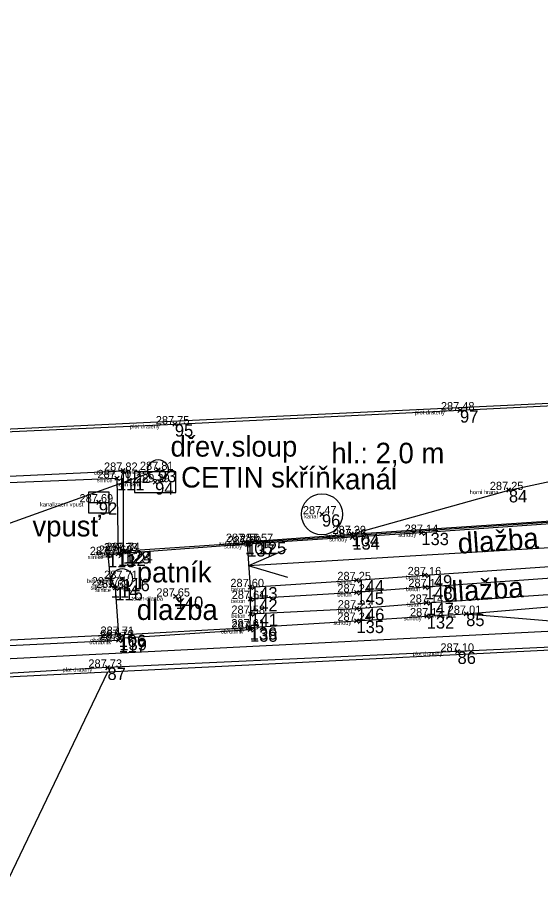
# Model space of a CAD drawing. Extents: x -456675 to -456278, y -1112395 to -1112217.
# Drawn here: x -456350.1 to -456337.38, y -1112310.69 to -1112289.29 of the extents above; entities that cross this region are included whole.
import ezdxf

# ---------------------------------------------------------------- set-up
doc = ezdxf.new("R2010")
doc.units = 0
for name, color, linetype in [('Cislo_bodu', 7, 'Continuous'), ('g_beton', 7, 'Continuous'), ('g_CETIN', 7, 'Continuous'), ('g_chodniky', 7, 'Continuous'), ('g_dalsi_prvky_polohopisu', 7, 'Continuous'), ('g_elektrina', 7, 'Continuous'), ('g_kanalizace', 7, 'Continuous'), ('g_komunikace', 7, 'Continuous'), ('g_obrubnik', 7, 'Continuous'), ('g_ploty', 7, 'Continuous'), ('g_schody', 7, 'Continuous'), ('g_terenni_hrany', 7, 'Continuous'), ('g_zabradli', 7, 'Continuous'), ('Katastralni_mapa', 7, 'Continuous'), ('Kod_bodu', 7, 'Continuous'), ('Vyska_bodu', 7, 'Continuous'), ('Znacka_bodu', 7, 'Continuous')]:
    doc.layers.add(name, color=color, linetype=linetype)

msp = doc.modelspace()

# ---------------------------------------------------------------- linework, layer by layer
at = {"layer": 'g_beton'}
for points in [[(-456344.443, -1112303.14), (-456341.853, -1112302.97), (-456340.193, -1112302.85), (-456332.603, -1112302.32), (-456329.373, -1112302.34)], [(-456329.383, -1112302.68), (-456332.633, -1112302.61), (-456340.183, -1112303.14), (-456341.853, -1112303.27), (-456344.443, -1112303.43)], [(-456344.433, -1112303.79), (-456341.843, -1112303.66), (-456340.153, -1112303.52), (-456332.693, -1112303.01), (-456329.403, -1112303.02)]]:
    msp.add_lwpolyline(points, dxfattribs=at)
at = {"layer": 'g_CETIN'}
msp.add_line((-456361.003, -1112305.42), (-456346.683, -1112300.29), dxfattribs=at)
msp.add_lwpolyline([(-456347.253, -1112300.84), (-456346.253, -1112300.84), (-456346.253, -1112300.34), (-456347.253, -1112300.34)], close=True, dxfattribs=at)
msp.add_circle((-456346.683, -1112300.29), 0.25, dxfattribs=at)
at = {"layer": 'g_chodniky'}
for p, q in [((-456344.513, -1112302.1), (-456347.653, -1112302.33)), ((-456347.643, -1112304.3), (-456344.453, -1112304.12))]:
    msp.add_line(p, q, dxfattribs=at)
at = {"layer": 'g_dalsi_prvky_polohopisu'}
for radius in [0.25, 0.0005]:
    msp.add_circle((-456347.554, -1112302.94), radius, dxfattribs=at)
at = {"layer": 'g_elektrina'}
msp.add_line((-456361.003, -1112305.42), (-456332.123, -1112303.96), dxfattribs=at)
at = {"layer": 'g_kanalizace'}
msp.add_line((-456348.373, -1112301.08), (-456347.873, -1112301.08), dxfattribs=at)
msp.add_lwpolyline([(-456348.373, -1112301.331), (-456347.873, -1112301.331), (-456347.873, -1112300.829), (-456348.373, -1112300.829)], close=True, dxfattribs=at)
msp.add_circle((-456342.693, -1112301.37), 0.5, dxfattribs=at)
at = {"layer": 'g_komunikace'}
msp.add_lwpolyline([(-456358.663, -1112300.93), (-456352.743, -1112300.69), (-456347.683, -1112300.49), (-456347.653, -1112302.33), (-456347.903, -1112302.36), (-456347.833, -1112303.1), (-456347.723, -1112303.16), (-456347.643, -1112304.3), (-456353.213, -1112304.58), (-456358.903, -1112304.84)], dxfattribs=at)
at = {"layer": 'g_obrubnik'}
msp.add_line((-456347.623, -1112304.38), (-456344.443, -1112304.17), dxfattribs=at)
for points in [[(-456358.623, -1112300.79), (-456352.573, -1112300.55), (-456347.533, -1112300.31), (-456347.533, -1112302.27)], [(-456347.483, -1112302.26), (-456344.233, -1112302.04), (-456332.683, -1112301.25), (-456329.463, -1112301.08)], [(-456358.943, -1112304.97), (-456353.293, -1112304.71), (-456347.643, -1112304.43)]]:
    msp.add_lwpolyline(points, dxfattribs=at)
at = {"layer": 'g_ploty'}
for points in [[(-456357.813, -1112299.7), (-456346.273, -1112299.18), (-456339.333, -1112298.84), (-456333.013, -1112298.52), (-456332.843, -1112291.41), (-456332.833, -1112287.66)], [(-456333.393, -1112317.5), (-456333.293, -1112310.05), (-456333.243, -1112304.42), (-456339.393, -1112304.71), (-456347.913, -1112305.1), (-456359.473, -1112305.79)]]:
    msp.add_lwpolyline(points, dxfattribs=at)
at = {"layer": 'g_schody'}
for p in [(-456329.348, -1112301.72), (-456343.561, -1112302.223), (-456343.52, -1112302.906)]:
    msp.add_line(p, (-456344.478, -1112302.62), dxfattribs=at)
msp.add_lwpolyline([(-456329.323, -1112301.1), (-456332.583, -1112301.31), (-456334.213, -1112301.4), (-456340.273, -1112301.82), (-456341.953, -1112301.93), (-456344.513, -1112302.1), (-456344.443, -1112303.14), (-456344.443, -1112303.43), (-456344.433, -1112303.79), (-456344.453, -1112304.12), (-456341.853, -1112303.96), (-456340.143, -1112303.85), (-456339.183, -1112303.79), (-456334.113, -1112303.36), (-456332.663, -1112303.3), (-456329.413, -1112303.32)], dxfattribs=at)
at = {"layer": 'g_terenni_hrany'}
for points in [[(-456341.973, -1112301.85), (-456338.143, -1112300.78), (-456332.883, -1112299.66), (-456333.013, -1112298.52)], [(-456339.183, -1112303.79), (-456332.533, -1112304.34), (-456333.293, -1112310.05)]]:
    msp.add_lwpolyline(points, dxfattribs=at)
at = {"layer": 'g_zabradli'}
msp.add_lwpolyline([(-456344.563, -1112302.04), (-456341.973, -1112301.85), (-456332.613, -1112301.23), (-456330.963, -1112301.12), (-456329.823, -1112301.04)], dxfattribs=at)
at = {"layer": 'Katastralni_mapa'}
for points in [[(-456333.073, -1112298.48), (-456362.193, -1112299.87)], [(-456347.903, -1112305.2), (-456333.213, -1112304.47)], [(-456369.703, -1112306.28), (-456347.903, -1112305.2)], [(-456359.693, -1112329.78), (-456347.903, -1112305.2)]]:
    msp.add_lwpolyline(points, dxfattribs=at)
at = {"layer": 'Znacka_bodu'}
for p, q in [((-456339.333, -1112298.84), (-456339.383, -1112298.79)), ((-456339.333, -1112298.84), (-456339.283, -1112298.79)), ((-456339.333, -1112298.84), (-456339.383, -1112298.89)), ((-456339.333, -1112298.84), (-456339.283, -1112298.89)), ((-456346.273, -1112299.18), (-456346.323, -1112299.13)), ((-456346.273, -1112299.18), (-456346.323, -1112299.23)), ((-456346.273, -1112299.18), (-456346.223, -1112299.13)), ((-456346.273, -1112299.18), (-456346.223, -1112299.23)), ((-456347.533, -1112300.31), (-456347.583, -1112300.26)), ((-456347.533, -1112300.31), (-456347.483, -1112300.26)), ((-456346.683, -1112300.29), (-456346.733, -1112300.24)), ((-456346.683, -1112300.29), (-456346.733, -1112300.34)), ((-456346.683, -1112300.29), (-456346.633, -1112300.24)), ((-456346.683, -1112300.29), (-456346.633, -1112300.34)), ((-456347.683, -1112300.49), (-456347.733, -1112300.44)), ((-456347.683, -1112300.49), (-456347.733, -1112300.54)), ((-456347.683, -1112300.49), (-456347.633, -1112300.44)), ((-456347.683, -1112300.49), (-456347.633, -1112300.54)), ((-456347.533, -1112300.31), (-456347.583, -1112300.36)), ((-456347.533, -1112300.31), (-456347.483, -1112300.36)), ((-456346.753, -1112300.59), (-456346.803, -1112300.54)), ((-456346.753, -1112300.59), (-456346.803, -1112300.64)), ((-456346.753, -1112300.59), (-456346.703, -1112300.54)), ((-456346.753, -1112300.59), (-456346.703, -1112300.64)), ((-456338.143, -1112300.78), (-456338.193, -1112300.73)), ((-456338.143, -1112300.78), (-456338.193, -1112300.83)), ((-456338.143, -1112300.78), (-456338.093, -1112300.73)), ((-456338.143, -1112300.78), (-456338.093, -1112300.83)), ((-456348.123, -1112301.08), (-456348.173, -1112301.03)), ((-456348.123, -1112301.08), (-456348.173, -1112301.13)), ((-456348.123, -1112301.08), (-456348.073, -1112301.03)), ((-456348.123, -1112301.08), (-456348.073, -1112301.13)), ((-456342.693, -1112301.37), (-456342.743, -1112301.32)), ((-456342.693, -1112301.37), (-456342.643, -1112301.32)), ((-456342.693, -1112301.37), (-456342.743, -1112301.42)), ((-456342.693, -1112301.37), (-456342.643, -1112301.42)), ((-456340.273, -1112301.82), (-456340.323, -1112301.77)), ((-456340.273, -1112301.82), (-456340.223, -1112301.77)), ((-456344.563, -1112302.04), (-456344.613, -1112301.99)), ((-456344.563, -1112302.04), (-456344.513, -1112301.99)), ((-456344.233, -1112302.04), (-456344.283, -1112301.99)), ((-456344.233, -1112302.04), (-456344.183, -1112301.99)), ((-456341.973, -1112301.85), (-456342.023, -1112301.8)), ((-456341.973, -1112301.85), (-456342.023, -1112301.9)), ((-456341.953, -1112301.93), (-456342.003, -1112301.88)), ((-456341.953, -1112301.93), (-456342.003, -1112301.98)), ((-456341.973, -1112301.85), (-456341.923, -1112301.8)), ((-456341.973, -1112301.85), (-456341.923, -1112301.9)), ((-456341.953, -1112301.93), (-456341.903, -1112301.88)), ((-456341.953, -1112301.93), (-456341.903, -1112301.98)), ((-456340.273, -1112301.82), (-456340.323, -1112301.87)), ((-456340.273, -1112301.82), (-456340.223, -1112301.87)), ((-456347.533, -1112302.27), (-456347.583, -1112302.22)), ((-456347.483, -1112302.26), (-456347.533, -1112302.21)), ((-456347.533, -1112302.27), (-456347.483, -1112302.22)), ((-456347.483, -1112302.26), (-456347.433, -1112302.21)), ((-456344.563, -1112302.04), (-456344.613, -1112302.09)), ((-456344.563, -1112302.04), (-456344.513, -1112302.09)), ((-456344.513, -1112302.1), (-456344.563, -1112302.05)), ((-456344.513, -1112302.1), (-456344.563, -1112302.15)), ((-456344.513, -1112302.1), (-456344.463, -1112302.05)), ((-456344.513, -1112302.1), (-456344.463, -1112302.15)), ((-456344.233, -1112302.04), (-456344.283, -1112302.09)), ((-456344.233, -1112302.04), (-456344.183, -1112302.09)), ((-456347.903, -1112302.36), (-456347.953, -1112302.31)), ((-456347.903, -1112302.36), (-456347.953, -1112302.41)), ((-456347.903, -1112302.36), (-456347.853, -1112302.31)), ((-456347.903, -1112302.36), (-456347.853, -1112302.41)), ((-456347.653, -1112302.33), (-456347.703, -1112302.28)), ((-456347.653, -1112302.33), (-456347.703, -1112302.38)), ((-456347.653, -1112302.33), (-456347.603, -1112302.28)), ((-456347.653, -1112302.33), (-456347.603, -1112302.38)), ((-456347.533, -1112302.27), (-456347.583, -1112302.32)), ((-456347.483, -1112302.26), (-456347.533, -1112302.31)), ((-456347.533, -1112302.27), (-456347.483, -1112302.32)), ((-456347.483, -1112302.26), (-456347.433, -1112302.31)), ((-456340.193, -1112302.85), (-456340.243, -1112302.8)), ((-456340.193, -1112302.85), (-456340.243, -1112302.9)), ((-456340.193, -1112302.85), (-456340.143, -1112302.8)), ((-456340.193, -1112302.85), (-456340.143, -1112302.9)), ((-456347.833, -1112303.1), (-456347.883, -1112303.05)), ((-456347.833, -1112303.1), (-456347.783, -1112303.05)), ((-456347.553, -1112302.94), (-456347.603, -1112302.89)), ((-456347.553, -1112302.94), (-456347.603, -1112302.99)), ((-456347.553, -1112302.94), (-456347.503, -1112302.89)), ((-456347.553, -1112302.94), (-456347.503, -1112302.99)), ((-456341.853, -1112302.97), (-456341.903, -1112302.92)), ((-456341.853, -1112302.97), (-456341.903, -1112303.02)), ((-456341.853, -1112302.97), (-456341.803, -1112302.92)), ((-456341.853, -1112302.97), (-456341.803, -1112303.02)), ((-456347.833, -1112303.1), (-456347.883, -1112303.15)), ((-456347.833, -1112303.1), (-456347.783, -1112303.15)), ((-456347.723, -1112303.16), (-456347.773, -1112303.11)), ((-456347.723, -1112303.16), (-456347.773, -1112303.21)), ((-456347.723, -1112303.16), (-456347.673, -1112303.11)), ((-456347.723, -1112303.16), (-456347.673, -1112303.21)), ((-456344.443, -1112303.14), (-456344.493, -1112303.09)), ((-456344.443, -1112303.14), (-456344.493, -1112303.19)), ((-456344.443, -1112303.14), (-456344.393, -1112303.09)), ((-456344.443, -1112303.14), (-456344.393, -1112303.19)), ((-456341.853, -1112303.27), (-456341.903, -1112303.22)), ((-456341.853, -1112303.27), (-456341.903, -1112303.32)), ((-456341.853, -1112303.27), (-456341.803, -1112303.22)), ((-456341.853, -1112303.27), (-456341.803, -1112303.32)), ((-456340.183, -1112303.14), (-456340.233, -1112303.09)), ((-456340.183, -1112303.14), (-456340.233, -1112303.19)), ((-456340.183, -1112303.14), (-456340.133, -1112303.09)), ((-456340.183, -1112303.14), (-456340.133, -1112303.19)), ((-456346.253, -1112303.37), (-456346.303, -1112303.32)), ((-456346.253, -1112303.37), (-456346.303, -1112303.42)), ((-456346.253, -1112303.37), (-456346.203, -1112303.32)), ((-456346.253, -1112303.37), (-456346.203, -1112303.42)), ((-456344.443, -1112303.43), (-456344.493, -1112303.38)), ((-456344.443, -1112303.43), (-456344.493, -1112303.48)), ((-456344.443, -1112303.43), (-456344.393, -1112303.38)), ((-456344.443, -1112303.43), (-456344.393, -1112303.48)), ((-456340.153, -1112303.52), (-456340.203, -1112303.47)), ((-456340.153, -1112303.52), (-456340.103, -1112303.47)), ((-456341.843, -1112303.66), (-456341.893, -1112303.61)), ((-456341.843, -1112303.66), (-456341.893, -1112303.71)), ((-456341.843, -1112303.66), (-456341.793, -1112303.61)), ((-456341.843, -1112303.66), (-456341.793, -1112303.71)), ((-456340.153, -1112303.52), (-456340.203, -1112303.57)), ((-456340.153, -1112303.52), (-456340.103, -1112303.57)), ((-456344.433, -1112303.79), (-456344.483, -1112303.74)), ((-456344.433, -1112303.79), (-456344.483, -1112303.84)), ((-456344.433, -1112303.79), (-456344.383, -1112303.74)), ((-456344.433, -1112303.79), (-456344.383, -1112303.84)), ((-456341.853, -1112303.96), (-456341.903, -1112303.91)), ((-456341.853, -1112303.96), (-456341.803, -1112303.91)), ((-456340.143, -1112303.85), (-456340.193, -1112303.8)), ((-456340.143, -1112303.85), (-456340.193, -1112303.9)), ((-456340.143, -1112303.85), (-456340.093, -1112303.8)), ((-456340.143, -1112303.85), (-456340.093, -1112303.9)), ((-456339.183, -1112303.79), (-456339.233, -1112303.74)), ((-456339.183, -1112303.79), (-456339.233, -1112303.84)), ((-456339.183, -1112303.79), (-456339.133, -1112303.74)), ((-456339.183, -1112303.79), (-456339.133, -1112303.84)), ((-456344.453, -1112304.12), (-456344.503, -1112304.07)), ((-456344.453, -1112304.12), (-456344.503, -1112304.17)), ((-456344.443, -1112304.17), (-456344.493, -1112304.12)), ((-456344.453, -1112304.12), (-456344.403, -1112304.07)), ((-456344.453, -1112304.12), (-456344.403, -1112304.17)), ((-456344.443, -1112304.17), (-456344.393, -1112304.12)), ((-456341.853, -1112303.96), (-456341.903, -1112304.01)), ((-456341.853, -1112303.96), (-456341.803, -1112304.01)), ((-456347.643, -1112304.3), (-456347.693, -1112304.25)), ((-456347.643, -1112304.3), (-456347.693, -1112304.35)), ((-456347.623, -1112304.38), (-456347.673, -1112304.33)), ((-456347.643, -1112304.3), (-456347.593, -1112304.25)), ((-456347.643, -1112304.3), (-456347.593, -1112304.35)), ((-456347.623, -1112304.38), (-456347.573, -1112304.33)), ((-456344.443, -1112304.17), (-456344.493, -1112304.22)), ((-456344.443, -1112304.17), (-456344.393, -1112304.22)), ((-456347.643, -1112304.43), (-456347.693, -1112304.38)), ((-456347.643, -1112304.43), (-456347.693, -1112304.48)), ((-456347.623, -1112304.38), (-456347.673, -1112304.43)), ((-456347.643, -1112304.43), (-456347.593, -1112304.38)), ((-456347.643, -1112304.43), (-456347.593, -1112304.48)), ((-456347.623, -1112304.38), (-456347.573, -1112304.43)), ((-456339.393, -1112304.71), (-456339.443, -1112304.66)), ((-456339.393, -1112304.71), (-456339.443, -1112304.76)), ((-456339.393, -1112304.71), (-456339.343, -1112304.66)), ((-456339.393, -1112304.71), (-456339.343, -1112304.76)), ((-456347.913, -1112305.1), (-456347.963, -1112305.05)), ((-456347.913, -1112305.1), (-456347.963, -1112305.15)), ((-456347.913, -1112305.1), (-456347.863, -1112305.05)), ((-456347.913, -1112305.1), (-456347.863, -1112305.15))]:
    msp.add_line(p, q, dxfattribs=at)

# ---------------------------------------------------------------- texts
at = {"layer": 'Cislo_bodu'}
for s, p in [('97', (-456339.333, -1112299.14)), ('95', (-456346.273, -1112299.48)), ('93', (-456346.683, -1112300.59)), ('111', (-456347.683, -1112300.79)), ('122', (-456347.533, -1112300.61)), ('94', (-456346.753, -1112300.89)), ('84', (-456338.143, -1112301.08)), ('92', (-456348.123, -1112301.38)), ('96', (-456342.693, -1112301.67)), ('104', (-456341.973, -1112302.15)), ('134', (-456341.953, -1112302.23)), ('133', (-456340.273, -1112302.12)), ('105', (-456344.563, -1112302.34)), ('137', (-456344.513, -1112302.4)), ('125', (-456344.233, -1112302.34)), ('113', (-456347.903, -1112302.66)), ('112', (-456347.653, -1112302.63)), ('123', (-456347.533, -1112302.57)), ('124', (-456347.483, -1112302.56)), ('149', (-456340.193, -1112303.15)), ('116', (-456347.553, -1112303.24)), ('144', (-456341.853, -1112303.27)), ('114', (-456347.833, -1112303.4)), ('115', (-456347.723, -1112303.46)), ('143', (-456344.443, -1112303.44)), ('145', (-456341.853, -1112303.57)), ('148', (-456340.183, -1112303.44)), ('140', (-456346.253, -1112303.67)), ('142', (-456344.443, -1112303.73)), ('146', (-456341.843, -1112303.96)), ('147', (-456340.153, -1112303.82)), ('141', (-456344.433, -1112304.09)), ('132', (-456340.143, -1112304.15)), ('85', (-456339.183, -1112304.09)), ('136', (-456344.453, -1112304.42)), ('135', (-456341.853, -1112304.26)), ('106', (-456347.643, -1112304.6)), ('138', (-456344.443, -1112304.47)), ('117', (-456347.643, -1112304.73)), ('139', (-456347.623, -1112304.68)), ('86', (-456339.393, -1112305.01)), ('87', (-456347.913, -1112305.4))]:
    msp.add_text(s, height=0.3, dxfattribs=at).set_placement(p)
at = {"layer": 'g_CETIN'}
for s, p in [('dřev.sloup', (-456346.379, -1112299.967)), ('CETIN skříň', (-456346.122, -1112300.719))]:
    msp.add_text(s, height=0.5, dxfattribs=at).set_placement(p)
at = {"layer": 'g_chodniky'}
msp.add_text('dlažba', height=0.5, dxfattribs=at).set_placement((-456347.201, -1112303.94))
at = {"layer": 'g_dalsi_prvky_polohopisu'}
msp.add_text('patník', height=0.5, dxfattribs=at).set_placement((-456347.201, -1112303.028))
at = {"layer": 'g_kanalizace'}
for s, p in [('hl.: 2,0 m', (-456342.465, -1112300.13)), ('kanál', (-456342.465, -1112300.765)), ('vpusť', (-456349.739, -1112301.908))]:
    msp.add_text(s, height=0.5, dxfattribs=at).set_placement(p)
at = {"layer": 'g_schody'}
for rotation, p in [(4.1708, (-456339.371, -1112302.332)), (3.7062, (-456339.74, -1112303.513))]:
    msp.add_text('dlažba', height=0.5, rotation=rotation, dxfattribs=at).set_placement(p)
at = {"layer": 'Kod_bodu'}
for s, p in [('plot drateny', (-456340.426, -1112298.94)), ('plot drateny', (-456347.366, -1112299.28)), ('drev.sloup', (-456347.523, -1112300.39)), ('obrubnik', (-456348.244, -1112300.41)), ('silnice', (-456348.174, -1112300.59)), ('cetin skrin', (-456347.708, -1112300.69)), ('horni hrana', (-456339.099, -1112300.88)), ('kanalizacni vpust', (-456349.555, -1112301.18)), ('kanal', (-456343.126, -1112301.47)), ('zabradli', (-456342.616, -1112301.95)), ('schody', (-456342.516, -1112302.03)), ('schody', (-456340.836, -1112301.92)), ('zabradli', (-456345.206, -1112302.14)), ('schody', (-456345.076, -1112302.2)), ('obrubnik', (-456344.944, -1112302.14)), ('silnice', (-456348.394, -1112302.46)), ('obrubnik', (-456348.244, -1112302.37)), ('obrubnik', (-456348.194, -1112302.36)), ('silnice', (-456348.144, -1112302.43)), ('beton', (-456340.659, -1112302.95)), ('bet.patnik', (-456348.411, -1112303.04)), ('beton', (-456342.319, -1112303.07)), ('silnice', (-456348.324, -1112303.2)), ('silnice', (-456348.214, -1112303.26)), ('beton', (-456344.909, -1112303.24)), ('beton', (-456342.319, -1112303.37)), ('beton', (-456340.649, -1112303.24)), ('teren-dlazba', (-456347.33, -1112303.47)), ('beton', (-456344.909, -1112303.53)), ('beton', (-456342.309, -1112303.76)), ('beton', (-456340.619, -1112303.62)), ('beton', (-456344.899, -1112303.89)), ('schody', (-456340.706, -1112303.95)), ('horni hrana', (-456340.139, -1112303.89)), ('schody', (-456345.016, -1112304.22)), ('schody', (-456342.416, -1112304.06)), ('silnice', (-456348.134, -1112304.4)), ('obrubnik', (-456345.154, -1112304.27)), ('obrubnik', (-456348.354, -1112304.53)), ('obrubnik', (-456348.334, -1112304.48)), ('plot drateny', (-456340.486, -1112304.81)), ('plot drateny', (-456349.006, -1112305.2))]:
    msp.add_text(s, height=0.1, dxfattribs=at).set_placement(p)
at = {"layer": 'Vyska_bodu'}
for s, p in [('287.48', (-456339.798, -1112298.84)), ('287.75', (-456346.738, -1112299.18)), ('287.70', (-456348.157, -1112300.49)), ('287.82', (-456347.998, -1112300.31)), ('287.81', (-456347.124, -1112300.29)), ('289.39', (-456347.219, -1112300.59)), ('287.25', (-456338.608, -1112300.78)), ('287.69', (-456348.594, -1112301.08)), ('287.47', (-456343.158, -1112301.37)), ('287.29', (-456342.439, -1112301.85)), ('287.26', (-456342.423, -1112301.93)), ('287.14', (-456340.681, -1112301.82)), ('287.56', (-456345.033, -1112302.04)), ('287.60', (-456344.992, -1112302.1)), ('287.57', (-456344.698, -1112302.04)), ('287.71', (-456348.344, -1112302.36)), ('287.69', (-456348.124, -1112302.33)), ('287.78', (-456347.998, -1112302.27)), ('287.74', (-456347.948, -1112302.26)), ('287.16', (-456340.607, -1112302.85)), ('287.71', (-456347.994, -1112302.94)), ('287.25', (-456342.318, -1112302.97)), ('287.72', (-456348.298, -1112303.1)), ('287.69', (-456348.194, -1112303.16)), ('287.60', (-456344.922, -1112303.14)), ('287.24', (-456342.318, -1112303.27)), ('287.14', (-456340.591, -1112303.14)), ('287.65', (-456346.723, -1112303.37)), ('287.61', (-456344.89, -1112303.43)), ('287.23', (-456342.308, -1112303.66)), ('287.14', (-456340.561, -1112303.52)), ('287.58', (-456344.898, -1112303.79)), ('287.12', (-456340.551, -1112303.85)), ('287.01', (-456339.633, -1112303.79)), ('287.61', (-456344.9, -1112304.12)), ('287.24', (-456342.318, -1112303.96)), ('287.71', (-456348.084, -1112304.3)), ('287.61', (-456344.89, -1112304.17)), ('287.78', (-456348.108, -1112304.43)), ('287.72', (-456348.088, -1112304.38)), ('287.10', (-456339.81, -1112304.71)), ('287.73', (-456348.378, -1112305.1))]:
    msp.add_text(s, height=0.2, dxfattribs=at).set_placement(p)

doc.saveas('drawing.dxf')
